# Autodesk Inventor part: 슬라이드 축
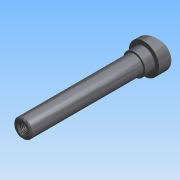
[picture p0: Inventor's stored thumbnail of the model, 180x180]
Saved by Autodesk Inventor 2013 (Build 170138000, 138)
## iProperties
Created: 2012-05
Part Number: 슬라이드 축
Document SubType Name: 모델링
Designer: SeoGD™
Mass: 169.556 g
Surface Area: 67.5858 cm^2
Volume: 21.572 cm^3
Density: 7.86 g/cm^3
Material: 강철, 연강
변환 표준: STEP AP214IS
파일 이름: C:\Users\SeoGD\Desktop\?쒗뿕\異?stp
전처리기: Build: 253, Release: 2010 SP1 - Date: Wed 07/29/2009
전송 단위: 밀리미터
불확실성: 0.01
Author: SeoGD™
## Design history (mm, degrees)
sketch "스케치1"
  geometry: L1 (0, 100)-(7.5, 100); L2 (7.5, 100)-(7.5, 0); L3 (7.5, 0)-(12.5, 0); L4 (12.5, 0)-(12.5, -17); L5 (12.5, -17)-(0, -17); L6 (0, -17)-(0, 100); 1 further point
  constraints: 12 end point, 2 parallel, 2 point on line, 1 perpendicular, 1 vertical
  dimensions: "d0" = 100 distance from line of L1 point (0, 0); "d1" = 15 diameter of L2 L6; "d2" = 25 diameter of L4 L6; "d3" = 17 distance of L3.end L4.end
revolve "회전1" sketch "스케치1" stored, may be unused: angle "d4" = 90 deg
sketch "스케치2"
  geometry: L1 (12.5, 0)-(12.5, -17) reference; L2 (-12.5, -17)-(12.5, -17) reference; L3 (-12.5, 0)-(-12.5, -17) reference; L4 (12.5, -5)-(-12.5, -11.699); L5 (-12.5, 0)-(12.5, 0) reference; 1 further point
  constraints: 2 end point, 2 point on line
  dimensions: "d5" = 75 deg angle of L1 L4; "d6" = 5 distance from line of L4.start L5
extrude "돌출1" cut sketch "스케치2" stored distance "d7" = 10; taper "d8" = 0 deg
chamfer "모따기1" distance "d9" = 1; stored, may be unused: second distance "d10" = 2, angle "d11" = 45 deg
fillet "모깎기1" dims "d12" = 0.5
hole "구멍1" diameter "d15" = 6.647; stored, may be unused: countersink angle "d19" = 90 deg, drill point angle "d21" = 118 deg; dims "d13" = 10, "d14" = 10, "d16" = 17, "d17" = 4, "d18" = 2, "d20" = 20
chamfer "모따기2" distance "d22" = 1; stored, may be unused: second distance "d23" = 2, angle "d24" = 45 deg
sketch "스케치3"
  geometry: C1 r 9 at (0, 0); 1 further point
  constraints: 1 centre point, 1 coincident
  dimensions: "d25" = 18 diameter of C1
extrude "돌출2" join sketch "스케치3" distance "d26" = 8; taper "d27" = 0 deg
node "솔리드1"
node "솔리드 본체"
node "곡면 본체"
node "솔리드2"
